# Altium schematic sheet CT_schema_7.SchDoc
size 287 x 160 mm
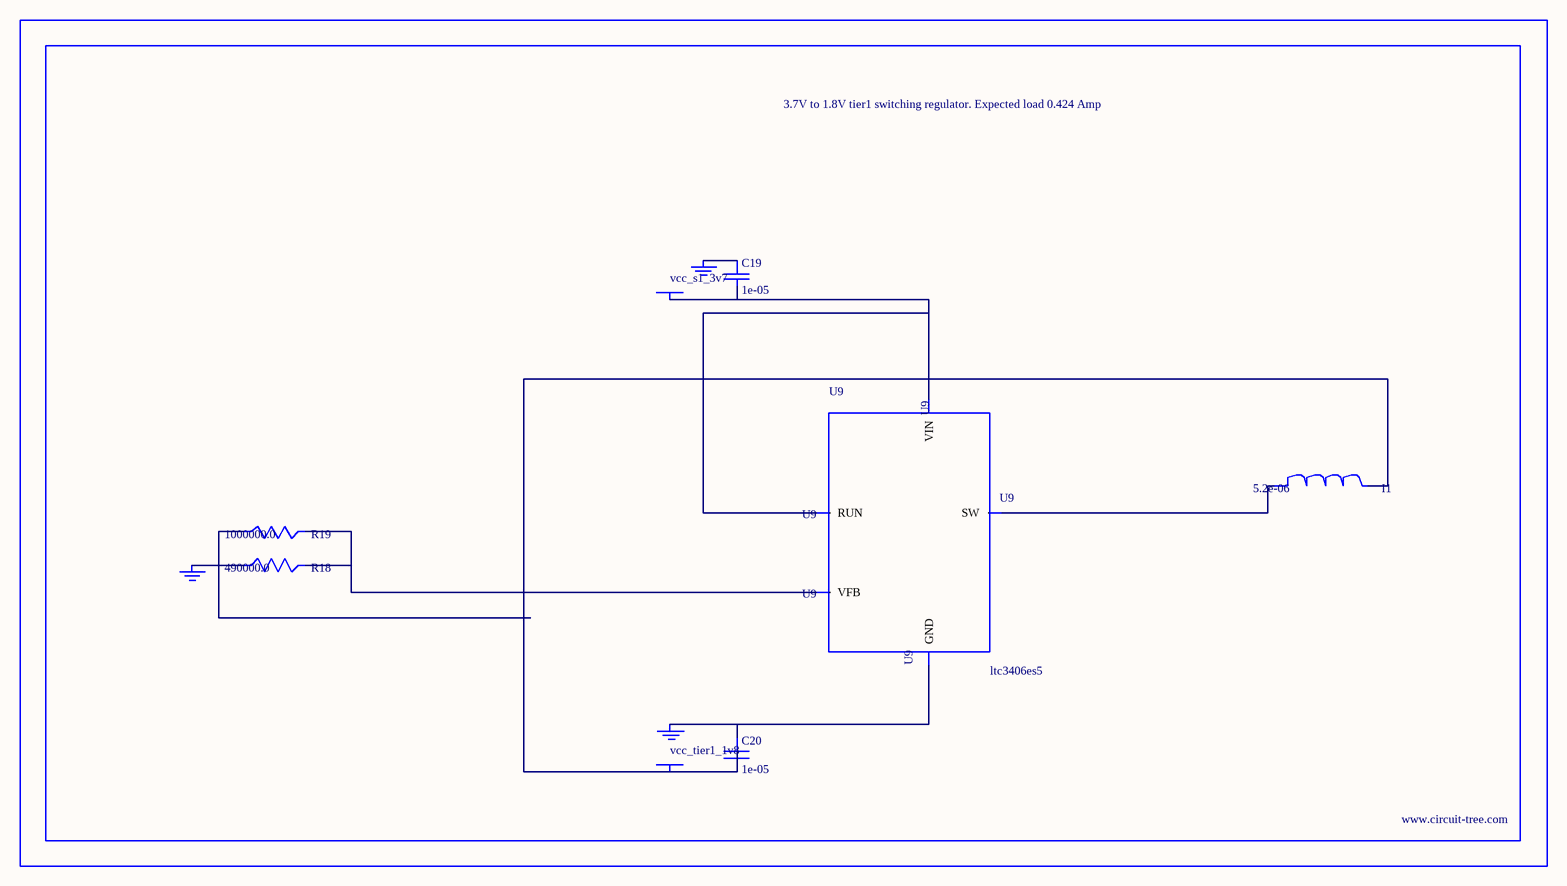
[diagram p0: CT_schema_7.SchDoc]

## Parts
BORDER6  (no value)
C19  1e-05  [C0805]
C20  1e-05  [C0805]
GND_INSTANCE_6_0  (no value)
GND_INSTANCE_6_1  (no value)
GND_INSTANCE_6_2  (no value)
I1  5.2e-06  [DR1040]
POWER_INSTANCE_6_0  vcc_tier1_1v8
POWER_INSTANCE_6_1  vcc_s1_3v7
R18  490000.0  [R0603]
R19  1000000.0  [R0603]
U9  ltc3406es5  [TSOT-23-5]

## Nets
NetC19_1: C19.1 GND_INSTANCE_6_1.0(GND)
NetC19_2: C19.2 POWER_INSTANCE_6_1.0(PWR) U9.1(RUN) U9.4(VIN)
NetC20_1: C20.1 GND_INSTANCE_6_0.0(GND) U9.2(GND)
NetC20_2: C20.2 I1.2 POWER_INSTANCE_6_0.0(PWR) R19.1
NetGND_INSTANCE_6_2_0: GND_INSTANCE_6_2.0(GND) R18.1
NetI1_1: I1.1 U9.3(SW)
NetR18_2: R18.2 R19.2 U9.5(VFB)

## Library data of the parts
BORDER6 = BORDER_PAGE6
C19 C20 = C0805C106K8RACTU
GND_INSTANCE_6_0-GND_INSTANCE_6_2 = GND
I1 = DR1040-5R2-R
POWER_INSTANCE_6_0 POWER_INSTANCE_6_1 = PWR
R18 = R18
R19 = RC0603JR-071ML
